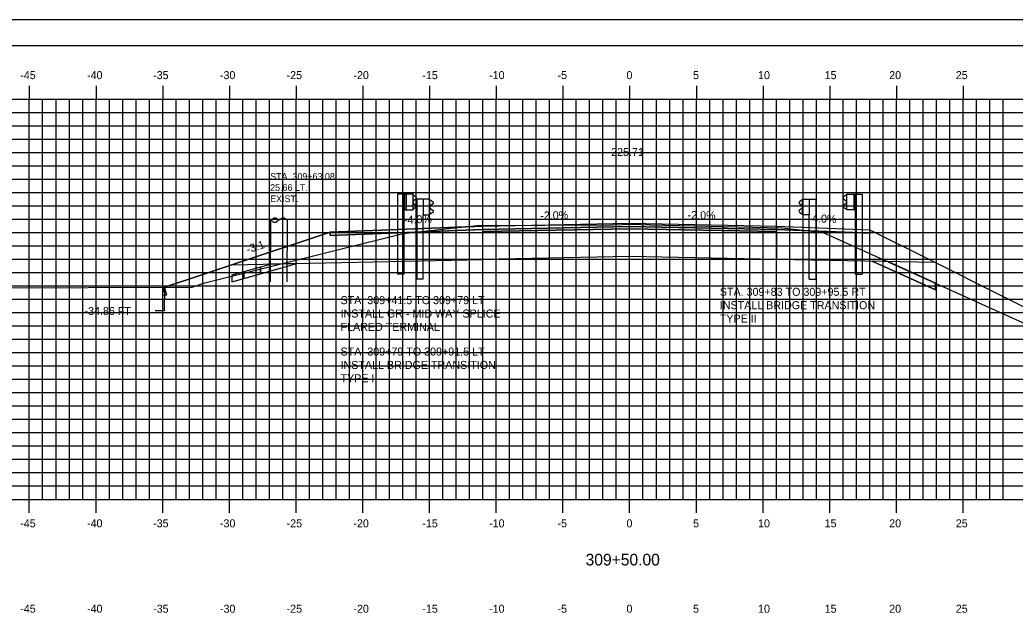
# Model space of a CAD drawing. Extents: x 1137876 to 1138046, y 608981 to 609091.
# Drawn here: x 1137913.5 to 1137988.1, y 609046.6 to 609091.3 of the extents above; entities that cross this region are included whole.
import ezdxf

# ---------------------------------------------------------------- set-up
doc = ezdxf.new("R2010")
doc.units = 0
for name, color, linetype in [('ANNOTATION', 7, 'Continuous'), ('BORDER', 7, 'Continuous'), ('D_Guardrail_Beam_Lt', 7, 'Continuous'), ('D_Guardrail_Beam_Rt', 7, 'Continuous'), ('D_Roadway_Centerline', 7, 'Continuous'), ('D_Roadway_Centerline_Text', 7, 'Continuous'), ('D_Roadway_Edge_Shoulder', 7, 'Continuous'), ('D_Roadway_Edge_TW', 7, 'Continuous'), ('D_Roadway_Pavement', 7, 'Continuous'), ('D_Roadway_SlopeLines', 7, 'Continuous'), ('D_Roadway_SubGrade', 7, 'Continuous'), ('D_Text_Monospaced', 7, 'Continuous'), ('D_Text_Standard', 7, 'Continuous'), ('H_V ANNOTATION', 7, 'Continuous'), ('MAJOR', 7, 'Continuous'), ('MINOR', 7, 'Continuous'), ('PLOT BOUNDARY', 7, 'Continuous'), ('S_Guardrail_Beam', 7, 'Continuous'), ('S_Roadway_Centerline', 7, 'Continuous'), ('S_Utilities_Pole_Power', 7, 'Continuous'), ('SHADING', 7, 'Continuous')]:
    doc.layers.add(name, color=color, linetype=linetype)

msp = doc.modelspace()

# ---------------------------------------------------------------- linework, layer by layer
msp.add_lwpolyline([(1137924.31, 609071.229), (1137926.339, 609071.906), (1137929.339, 609072.906), (1137936.714, 609075.364), (1137936.715, 609075.364), (1137948.166, 609075.822), (1137959.166, 609076.042), (1137970.166, 609075.822), (1137977.166, 609075.542), (1137982.083, 609073.084), (1137986.552, 609070.849), (1137995.165, 609066.543)])
at = {"layer": 'BORDER'}
msp.add_lwpolyline([(1137884.166, 608984.335), (1138044.166, 608984.335), (1138044.166, 609089.335), (1137884.166, 609089.335)], close=True, dxfattribs=at)
at = {"layer": 'D_Guardrail_Beam_Lt'}
for p, q in [((1137941.768, 609078.207), (1137941.768, 609072.207)), ((1137942.239, 609078.207), (1137941.768, 609078.207)), ((1137942.926, 609078.207), (1137942.239, 609078.207)), ((1137942.239, 609078.207), (1137942.239, 609077.04)), ((1137942.301, 609078.207), (1137942.301, 609077.04)), ((1137942.405, 609078.207), (1137942.405, 609077.04)), ((1137942.926, 609077.04), (1137942.926, 609078.207)), ((1137942.926, 609078.124), (1137943, 609078.109)), ((1137942.931, 609077.659), (1137942.931, 609077.589)), ((1137943.16, 609077.859), (1137942.964, 609077.723)), ((1137943.016, 609078.102), (1137943.16, 609078.003)), ((1137975.347, 609078.101), (1137975.203, 609078.001)), ((1137975.203, 609077.858), (1137975.399, 609077.722)), ((1137975.437, 609078.122), (1137975.363, 609078.108)), ((1137975.432, 609077.657), (1137975.432, 609077.587)), ((1137942.239, 609077.04), (1137942.926, 609077.04)), ((1137942.26, 609072.207), (1137942.26, 609077.04)), ((1137943, 609077.138), (1137942.926, 609077.124)), ((1137942.964, 609077.524), (1137943.16, 609077.388)), ((1137943.16, 609077.245), (1137943.016, 609077.145)), ((1137975.399, 609077.523), (1137975.203, 609077.386)), ((1137975.203, 609077.243), (1137975.347, 609077.143)), ((1137975.363, 609077.137), (1137975.437, 609077.122)), ((1137942.26, 609072.207), (1137941.768, 609072.207))]:
    msp.add_line(p, q, dxfattribs=at)
for centre, major_axis, start_param, end_param in [((1137943.01, 609077.659), (-0.0789, 0), 5.323254, 6.283185), ((1137942.992, 609078.069), (0.0417, 0), 0.959931, 1.376053), ((1137943.109, 609077.931), (0.0877, 0), 5.323254, 7.243116), ((1137975.254, 609077.929), (-0.0877, 0), 5.323254, 7.243116), ((1137975.371, 609078.067), (-0.0417, 0), 4.907132, 5.323254), ((1137975.353, 609077.657), (0.0789, 0), 0, 0.959931), ((1137943.01, 609077.589), (-0.0789, 0), 6.283185, 7.243116), ((1137942.992, 609077.179), (0.0417, 0), 4.907132, 5.323254), ((1137943.109, 609077.317), (0.0877, 0), 5.323254, 7.243116), ((1137975.254, 609077.315), (-0.0877, 0), 5.323254, 7.243116), ((1137975.371, 609077.177), (-0.0417, 0), 0.959931, 1.376053), ((1137975.353, 609077.587), (0.0789, 0), 5.323254, 6.283185)]:
    msp.add_ellipse(centre, major_axis=major_axis, ratio=0.995501, start_param=start_param, end_param=end_param, dxfattribs=at)
at = {"layer": 'D_Guardrail_Beam_Rt'}
for p, q in [((1137975.437, 609078.205), (1137976.124, 609078.205)), ((1137975.437, 609077.039), (1137975.437, 609078.205)), ((1137975.958, 609078.205), (1137975.958, 609077.039)), ((1137976.062, 609078.205), (1137976.062, 609077.039)), ((1137976.124, 609078.205), (1137976.595, 609078.205)), ((1137976.124, 609078.205), (1137976.124, 609077.039)), ((1137976.595, 609078.205), (1137976.595, 609072.205)), ((1137976.124, 609077.039), (1137975.437, 609077.039)), ((1137976.103, 609072.205), (1137976.103, 609077.039)), ((1137976.103, 609072.205), (1137976.595, 609072.205))]:
    msp.add_line(p, q, dxfattribs=at)
at = {"layer": 'D_Roadway_Edge_Shoulder'}
for points in [[(1137948.166, 609075.822), (1137936.715, 609075.364), (1137936.715, 609075.114), (1137948.166, 609075.572)], [(1137970.166, 609075.822), (1137977.166, 609075.542), (1137977.166, 609075.292), (1137970.166, 609075.572)]]:
    msp.add_lwpolyline(points, close=True, dxfattribs=at)
at = {"layer": 'D_Roadway_Edge_TW'}
msp.add_lwpolyline([(1137948.166, 609075.572), (1137948.166, 609075.822), (1137959.166, 609076.042), (1137970.166, 609075.822), (1137970.166, 609075.572), (1137959.166, 609075.792)], close=True, dxfattribs=at)
at = {"layer": 'D_Roadway_Pavement'}
msp.add_lwpolyline([(1137948.166, 609075.405), (1137948.166, 609075.572), (1137959.166, 609075.792), (1137970.166, 609075.572), (1137970.166, 609075.405), (1137959.166, 609075.625)], close=True, dxfattribs=at)
at = {"layer": 'D_Roadway_SlopeLines'}
for points in [[(1137982.083, 609071.538), (1137982.083, 609071.038), (1137977.351, 609073.178)], [(1137929.339, 609072.906), (1137926.339, 609071.906)], [(1137929.339, 609072.136), (1137929.339, 609071.636), (1137934.208, 609073.003)], [(1137982.083, 609073.084), (1137986.552, 609070.849)], [(1137926.339, 609071.906), (1137924.31, 609071.229)], [(1137986.552, 609070.849), (1137995.165, 609066.543)]]:
    msp.add_lwpolyline(points, dxfattribs=at)
at = {"layer": 'D_Roadway_SubGrade'}
for points in [[(1137948.166, 609075.405), (1137948.166, 609075.572), (1137936.715, 609075.114), (1137936.715, 609075.364), (1137936.714, 609075.364), (1137929.339, 609072.906), (1137948.166, 609073.322)], [(1137948.166, 609073.322), (1137948.166, 609075.405), (1137959.166, 609075.625), (1137970.166, 609075.405), (1137970.166, 609073.322), (1137959.166, 609073.542)], [(1137970.166, 609075.405), (1137970.166, 609075.572), (1137977.166, 609075.292), (1137977.166, 609075.542), (1137977.166, 609075.542), (1137982.083, 609073.084), (1137970.166, 609073.322)]]:
    msp.add_lwpolyline(points, close=True, dxfattribs=at)
at = {"layer": 'D_Text_Standard'}
msp.add_lwpolyline([(1137924.31, 609071.229), (1137924.285, 609069.455), (1137923.605, 609069.455)], dxfattribs=at)
msp.add_lwpolyline([(1137924.31, 609071.229), (1137924.447, 609070.645), (1137924.156, 609070.649)], close=True, dxfattribs=at)
at = {"layer": 'MAJOR'}
for p, q in [((1137914.166, 609086.337), (1137914.166, 609085.335)), ((1137919.166, 609086.337), (1137919.166, 609085.335)), ((1137924.166, 609086.337), (1137924.166, 609085.335)), ((1137929.166, 609086.337), (1137929.166, 609085.335)), ((1137934.166, 609086.337), (1137934.166, 609085.335)), ((1137939.166, 609086.337), (1137939.166, 609085.335)), ((1137944.166, 609086.337), (1137944.166, 609085.335)), ((1137949.166, 609086.337), (1137949.166, 609085.335)), ((1137954.166, 609086.337), (1137954.166, 609085.335)), ((1137959.166, 609086.337), (1137959.166, 609085.335)), ((1137964.166, 609086.337), (1137964.166, 609085.335)), ((1137969.166, 609086.337), (1137969.166, 609085.335)), ((1137974.166, 609086.337), (1137974.166, 609085.335)), ((1137979.166, 609086.337), (1137979.166, 609085.335)), ((1137984.166, 609086.337), (1137984.166, 609085.335)), ((1137889.166, 609085.335), (1138029.166, 609085.335)), ((1137889.166, 609085.335), (1138029.166, 609085.335)), ((1137914.166, 609055.335), (1137914.166, 609085.335)), ((1137919.166, 609055.335), (1137919.166, 609085.335)), ((1137924.166, 609055.335), (1137924.166, 609085.335)), ((1137929.166, 609055.335), (1137929.166, 609085.335)), ((1137934.166, 609055.335), (1137934.166, 609085.335)), ((1137939.166, 609055.335), (1137939.166, 609085.335)), ((1137944.166, 609055.335), (1137944.166, 609085.335)), ((1137949.166, 609055.335), (1137949.166, 609085.335)), ((1137954.166, 609055.335), (1137954.166, 609085.335)), ((1137959.166, 609055.335), (1137959.166, 609085.335)), ((1137964.166, 609055.335), (1137964.166, 609085.335)), ((1137969.166, 609055.335), (1137969.166, 609085.335)), ((1137974.166, 609055.335), (1137974.166, 609085.335)), ((1137979.166, 609055.335), (1137979.166, 609085.335)), ((1137984.166, 609055.335), (1137984.166, 609085.335)), ((1137889.166, 609080.335), (1138029.166, 609080.335)), ((1137889.166, 609075.335), (1138029.166, 609075.335)), ((1137889.166, 609070.335), (1138029.166, 609070.335)), ((1137889.166, 609065.335), (1138029.166, 609065.335)), ((1137889.166, 609060.335), (1138029.166, 609060.335)), ((1137889.166, 609055.335), (1138029.166, 609055.335)), ((1137889.166, 609055.335), (1138029.166, 609055.335)), ((1137914.166, 609054.333), (1137914.166, 609055.335)), ((1137919.166, 609054.333), (1137919.166, 609055.335)), ((1137924.166, 609054.333), (1137924.166, 609055.335)), ((1137929.166, 609054.333), (1137929.166, 609055.335)), ((1137934.166, 609054.333), (1137934.166, 609055.335)), ((1137939.166, 609054.333), (1137939.166, 609055.335)), ((1137944.166, 609054.333), (1137944.166, 609055.335)), ((1137949.166, 609054.333), (1137949.166, 609055.335)), ((1137954.166, 609054.333), (1137954.166, 609055.335)), ((1137959.166, 609054.333), (1137959.166, 609055.335)), ((1137964.166, 609054.333), (1137964.166, 609055.335)), ((1137969.166, 609054.333), (1137969.166, 609055.335)), ((1137974.166, 609054.333), (1137974.166, 609055.335)), ((1137979.166, 609054.333), (1137979.166, 609055.335)), ((1137984.166, 609054.333), (1137984.166, 609055.335))]:
    msp.add_line(p, q, dxfattribs=at)
at = {"layer": 'MINOR'}
for p, q in [((1137915.166, 609055.335), (1137915.166, 609085.335)), ((1137916.166, 609055.335), (1137916.166, 609085.335)), ((1137917.166, 609055.335), (1137917.166, 609085.335)), ((1137918.166, 609055.335), (1137918.166, 609085.335)), ((1137920.166, 609055.335), (1137920.166, 609085.335)), ((1137921.166, 609055.335), (1137921.166, 609085.335)), ((1137922.166, 609055.335), (1137922.166, 609085.335)), ((1137923.166, 609055.335), (1137923.166, 609085.335)), ((1137925.166, 609055.335), (1137925.166, 609085.335)), ((1137926.166, 609055.335), (1137926.166, 609085.335)), ((1137927.166, 609055.335), (1137927.166, 609085.335)), ((1137928.166, 609055.335), (1137928.166, 609085.335)), ((1137930.166, 609055.335), (1137930.166, 609085.335)), ((1137931.166, 609055.335), (1137931.166, 609085.335)), ((1137932.166, 609055.335), (1137932.166, 609085.335)), ((1137933.166, 609055.335), (1137933.166, 609085.335)), ((1137935.166, 609055.335), (1137935.166, 609085.335)), ((1137936.166, 609055.335), (1137936.166, 609085.335)), ((1137937.166, 609055.335), (1137937.166, 609085.335)), ((1137938.166, 609055.335), (1137938.166, 609085.335)), ((1137940.166, 609055.335), (1137940.166, 609085.335)), ((1137941.166, 609055.335), (1137941.166, 609085.335)), ((1137942.166, 609055.335), (1137942.166, 609085.335)), ((1137943.166, 609055.335), (1137943.166, 609085.335)), ((1137945.166, 609055.335), (1137945.166, 609085.335)), ((1137946.166, 609055.335), (1137946.166, 609085.335)), ((1137947.166, 609055.335), (1137947.166, 609085.335)), ((1137948.166, 609055.335), (1137948.166, 609085.335)), ((1137950.166, 609055.335), (1137950.166, 609085.335)), ((1137951.166, 609055.335), (1137951.166, 609085.335)), ((1137952.166, 609055.335), (1137952.166, 609085.335)), ((1137953.166, 609055.335), (1137953.166, 609085.335)), ((1137955.166, 609055.335), (1137955.166, 609085.335)), ((1137956.166, 609055.335), (1137956.166, 609085.335)), ((1137957.166, 609055.335), (1137957.166, 609085.335)), ((1137958.166, 609055.335), (1137958.166, 609085.335)), ((1137960.166, 609055.335), (1137960.166, 609085.335)), ((1137961.166, 609055.335), (1137961.166, 609085.335)), ((1137962.166, 609055.335), (1137962.166, 609085.335)), ((1137963.166, 609055.335), (1137963.166, 609085.335)), ((1137965.166, 609055.335), (1137965.166, 609085.335)), ((1137966.166, 609055.335), (1137966.166, 609085.335)), ((1137967.166, 609055.335), (1137967.166, 609085.335)), ((1137968.166, 609055.335), (1137968.166, 609085.335)), ((1137970.166, 609055.335), (1137970.166, 609085.335)), ((1137971.166, 609055.335), (1137971.166, 609085.335)), ((1137972.166, 609055.335), (1137972.166, 609085.335)), ((1137973.166, 609055.335), (1137973.166, 609085.335)), ((1137975.166, 609055.335), (1137975.166, 609085.335)), ((1137976.166, 609055.335), (1137976.166, 609085.335)), ((1137977.166, 609055.335), (1137977.166, 609085.335)), ((1137978.166, 609055.335), (1137978.166, 609085.335)), ((1137980.166, 609055.335), (1137980.166, 609085.335)), ((1137981.166, 609055.335), (1137981.166, 609085.335)), ((1137982.166, 609055.335), (1137982.166, 609085.335)), ((1137983.166, 609055.335), (1137983.166, 609085.335)), ((1137985.166, 609055.335), (1137985.166, 609085.335)), ((1137986.166, 609055.335), (1137986.166, 609085.335)), ((1137987.166, 609055.335), (1137987.166, 609085.335)), ((1137889.166, 609084.335), (1138029.166, 609084.335)), ((1137889.166, 609083.335), (1138029.166, 609083.335)), ((1137889.166, 609082.335), (1138029.166, 609082.335)), ((1137889.166, 609081.335), (1138029.166, 609081.335)), ((1137889.166, 609079.335), (1138029.166, 609079.335)), ((1137889.166, 609078.335), (1138029.166, 609078.335)), ((1137889.166, 609077.335), (1138029.166, 609077.335)), ((1137889.166, 609076.335), (1138029.166, 609076.335)), ((1137889.166, 609074.335), (1138029.166, 609074.335)), ((1137889.166, 609073.335), (1138029.166, 609073.335)), ((1137889.166, 609072.335), (1138029.166, 609072.335)), ((1137889.166, 609071.335), (1138029.166, 609071.335)), ((1137889.166, 609069.335), (1138029.166, 609069.335)), ((1137889.166, 609068.335), (1138029.166, 609068.335)), ((1137889.166, 609067.335), (1138029.166, 609067.335)), ((1137889.166, 609066.335), (1138029.166, 609066.335)), ((1137889.166, 609064.335), (1138029.166, 609064.335)), ((1137889.166, 609063.335), (1138029.166, 609063.335)), ((1137889.166, 609062.335), (1138029.166, 609062.335)), ((1137889.166, 609061.335), (1138029.166, 609061.335)), ((1137889.166, 609059.335), (1138029.166, 609059.335)), ((1137889.166, 609058.335), (1138029.166, 609058.335)), ((1137889.166, 609057.335), (1138029.166, 609057.335)), ((1137889.166, 609056.335), (1138029.166, 609056.335))]:
    msp.add_line(p, q, dxfattribs=at)
at = {"layer": 'PLOT BOUNDARY'}
msp.add_lwpolyline([(1137876.073, 608981.276), (1138046.073, 608981.276), (1138046.073, 609091.276), (1137876.073, 609091.276)], close=True, dxfattribs=at)
at = {"layer": 'S_Guardrail_Beam'}
for p, q in [((1137943.205, 609077.828), (1137943.205, 609071.828)), ((1137943.697, 609077.828), (1137943.205, 609077.828)), ((1137944.187, 609077.828), (1137943.697, 609077.828)), ((1137943.697, 609077.828), (1137943.697, 609076.661)), ((1137944.187, 609076.661), (1137944.187, 609077.828)), ((1137944.187, 609077.755), (1137944.269, 609077.74)), ((1137944.285, 609077.733), (1137944.429, 609077.633)), ((1137972.032, 609077.747), (1137971.889, 609077.647)), ((1137972.131, 609077.768), (1137972.049, 609077.754)), ((1137972.131, 609077.841), (1137972.62, 609077.841)), ((1137972.131, 609076.674), (1137972.131, 609077.841)), ((1137972.62, 609077.841), (1137973.112, 609077.841)), ((1137972.62, 609077.841), (1137972.62, 609076.674)), ((1137973.112, 609077.841), (1137973.112, 609071.841)), ((1137944.2, 609077.29), (1137944.2, 609077.199)), ((1137944.429, 609077.49), (1137944.233, 609077.354)), ((1137944.233, 609077.134), (1137944.429, 609076.998)), ((1137971.889, 609077.504), (1137972.084, 609077.367)), ((1137972.084, 609077.148), (1137971.889, 609077.011)), ((1137972.118, 609077.303), (1137972.118, 609077.212)), ((1137943.697, 609071.828), (1137943.697, 609076.661)), ((1137943.697, 609076.661), (1137944.187, 609076.661)), ((1137944.269, 609076.748), (1137944.187, 609076.734)), ((1137944.429, 609076.855), (1137944.285, 609076.755)), ((1137971.889, 609076.868), (1137972.032, 609076.768)), ((1137972.049, 609076.762), (1137972.131, 609076.747)), ((1137972.62, 609076.674), (1137972.131, 609076.674)), ((1137972.62, 609071.841), (1137972.62, 609076.674)), ((1137943.697, 609071.828), (1137943.205, 609071.828)), ((1137972.62, 609071.841), (1137973.112, 609071.841))]:
    msp.add_line(p, q, dxfattribs=at)
for centre, major_axis, start_param, end_param in [((1137944.261, 609077.699), (0.0417, 0), 0.959931, 1.396263), ((1137944.378, 609077.562), (0.0877, 0), 5.323254, 7.243116), ((1137971.939, 609077.575), (-0.0877, 0), 5.323254, 7.243116), ((1137972.056, 609077.713), (-0.0417, 0), 4.886922, 5.323254), ((1137944.279, 609077.29), (-0.0789, 0), 5.323254, 6.283185), ((1137944.279, 609077.199), (-0.0789, 0), 6.283185, 7.243116), ((1137944.378, 609076.927), (0.0877, 0), 5.323254, 7.243116), ((1137971.939, 609076.94), (-0.0877, 0), 5.323254, 7.243116), ((1137972.039, 609077.303), (0.0789, 0), 0, 0.959931), ((1137972.039, 609077.212), (0.0789, 0), 5.323254, 6.283185), ((1137944.261, 609076.789), (0.0417, 0), 4.886922, 5.323254), ((1137972.056, 609076.802), (-0.0417, 0), 0.959931, 1.396263)]:
    msp.add_ellipse(centre, major_axis=major_axis, ratio=0.995501, start_param=start_param, end_param=end_param, dxfattribs=at)
at = {"layer": 'S_Roadway_Centerline'}
msp.add_lwpolyline([(1137889.166, 609070.313), (1137894.157, 609070.541), (1137907.419, 609071.161), (1137910.439, 609071.192), (1137910.786, 609071.181), (1137926.383, 609071.246), (1137927.333, 609071.573), (1137942.192, 609075.263), (1137946.056, 609075.698), (1137947.752, 609075.86), (1137957.882, 609075.908), (1137959.356, 609075.955), (1137960.699, 609075.902), (1137970.583, 609075.689), (1137973.493, 609075.356), (1137973.722, 609075.319), (1137986.058, 609069.74), (1137991.281, 609067.381), (1137992.629, 609067.183), (1137998.236, 609065.767), (1138001.572, 609065.613), (1138013.791, 609064.771), (1138025.425, 609064.464), (1138029.166, 609064.258)], dxfattribs=at)
at = {"layer": 'S_Utilities_Pole_Power'}
for p, q in [((1137932.255, 609076.265), (1137932.411, 609076.375)), ((1137932.255, 609071.645), (1137932.258, 609076.265)), ((1137932.411, 609076.154), (1137932.255, 609076.265)), ((1137932.724, 609076.375), (1137932.88, 609076.265)), ((1137932.88, 609076.265), (1137932.724, 609076.154)), ((1137933.037, 609076.375), (1137932.88, 609076.265)), ((1137933.505, 609076.265), (1137933.349, 609076.375)), ((1137933.505, 609071.645), (1137933.508, 609076.265))]:
    msp.add_line(p, q, dxfattribs=at)
for centre, start, end in [((1137932.568, 609076.154), 90, 125.26439), ((1137932.568, 609076.375), 234.73561, 270), ((1137932.568, 609076.154), 54.73561, 90), ((1137932.568, 609076.375), 270, 305.26439), ((1137933.193, 609076.154), 90, 125.26439), ((1137933.193, 609076.154), 54.73561, 90)]:
    msp.add_arc(centre, 0.271, start, end, dxfattribs=at)
at = {"layer": 'SHADING'}
for p, q in [((1137978.507, 609073.155), (1137977.351, 609073.178)), ((1137931.506, 609072.744), (1137930.256, 609072.393)), ((1137931.506, 609072.244), (1137934.208, 609073.003)), ((1137932.291, 609072.965), (1137931.506, 609072.744)), ((1137931.506, 609072.744), (1137931.506, 609072.244)), ((1137931.506, 609072.244), (1137931.506, 609072.744)), ((1137934.208, 609073.003), (1137932.291, 609072.965)), ((1137982.083, 609071.538), (1137978.507, 609073.155)), ((1137930.256, 609072.393), (1137929.339, 609072.136)), ((1137930.256, 609072.393), (1137930.255, 609071.893)), ((1137930.255, 609071.893), (1137930.256, 609072.393)), ((1137930.255, 609071.893), (1137931.506, 609072.244))]:
    msp.add_line(p, q, dxfattribs=at)
for points in [[(1137977.351, 609073.178), (1137982.083, 609071.038), (1137982.083, 609071.538)], [(1137929.339, 609072.136), (1137929.339, 609071.636), (1137930.255, 609071.893)]]:
    msp.add_lwpolyline(points, dxfattribs=at)

# ---------------------------------------------------------------- texts
at = {"layer": 'ANNOTATION'}
for s, rotation, p in [('-2.0%', 1.14576, (1137952.469, 609076.308)), ('-2.0%', 358.85424, (1137963.509, 609076.355)), ('-4.0%', 2.29061, (1137942.257, 609075.987)), ('-4.0%', 357.70939, (1137972.562, 609076.127)), ('-3:1', 18.43483, (1137930.544, 609073.761))]:
    msp.add_text(s, height=0.6, rotation=rotation, dxfattribs=at).set_placement(p)
for s, p in [('STA. 309+83 TO 309+95.5 RT', (1137965.925, 609070.593)), ('STA. 309+41.5 TO 309+79 LT', (1137937.495, 609069.966)), ('INSTALL BRIDGE TRANSITION', (1137965.925, 609069.591)), ('INSTALL GR - MID WAY SPLICE', (1137937.495, 609068.964)), ('TYPE II', (1137965.925, 609068.589)), ('FLARED TERMINAL', (1137937.495, 609067.962)), ('STA. 309+79 TO 309+91.5 LT', (1137937.495, 609066.114)), ('INSTALL BRIDGE TRANSITION', (1137937.495, 609065.112)), ('TYPE II', (1137937.495, 609064.11))]:
    msp.add_text(s, height=0.6, dxfattribs=at).set_placement(p)
at = {"layer": 'D_Roadway_Centerline'}
for s, p in [('C', (1137959.161, 609076.042)), ('L', (1137959.166, 609076.035))]:
    msp.add_text(s, height=0.0146, dxfattribs=at).set_placement(p)
at = {"layer": 'D_Roadway_Centerline_Text'}
msp.add_text('225.71', height=0.6, dxfattribs=at).set_placement((1137957.78, 609081.074))
at = {"layer": 'D_Text_Monospaced'}
for s, height, p in [('STA. 309+63.08', 0.49998, (1137932.218, 609079.291)), ('25.66 LT.', 0.5, (1137932.218, 609078.457)), ('EXIST. ', 0.5, (1137932.218, 609077.617))]:
    msp.add_text(s, height=height, dxfattribs=at).set_placement(p)
at = {"layer": 'D_Text_Standard'}
msp.add_text('-34.86 FT', height=0.6, dxfattribs=at).set_placement((1137918.3, 609069.155))
at = {"layer": 'H_V ANNOTATION'}
for s, height, p in [('-45', 0.6, (1137913.484, 609086.835)), ('-40', 0.6, (1137918.492, 609086.835)), ('-35', 0.6, (1137923.446, 609086.835)), ('-30', 0.6, (1137928.454, 609086.835)), ('-25', 0.6, (1137933.451, 609086.835)), ('-20', 0.6, (1137938.459, 609086.835)), ('-15', 0.6, (1137943.623, 609086.835)), ('-10', 0.6, (1137948.631, 609086.835)), ('-5', 0.6, (1137953.757, 609086.835)), ('0', 0.6, (1137958.925, 609086.835)), ('5', 0.6, (1137963.917, 609086.835)), ('10', 0.6, (1137968.791, 609086.835)), ('15', 0.6, (1137973.783, 609086.835)), ('20', 0.6, (1137978.62, 609086.835)), ('25', 0.6, (1137983.612, 609086.835)), ('-45', 0.6, (1137913.484, 609053.235)), ('-40', 0.6, (1137918.492, 609053.235)), ('-35', 0.6, (1137923.446, 609053.235)), ('-30', 0.6, (1137928.454, 609053.235)), ('-25', 0.6, (1137933.451, 609053.235)), ('-20', 0.6, (1137938.459, 609053.235)), ('-15', 0.6, (1137943.623, 609053.235)), ('-10', 0.6, (1137948.631, 609053.235)), ('-5', 0.6, (1137953.757, 609053.235)), ('0', 0.6, (1137958.925, 609053.235)), ('5', 0.6, (1137963.917, 609053.235)), ('10', 0.6, (1137968.791, 609053.235)), ('15', 0.6, (1137973.783, 609053.235)), ('20', 0.6, (1137978.62, 609053.235)), ('25', 0.6, (1137983.612, 609053.235)), ('309+50.00', 0.875, (1137955.865, 609050.378)), ('-45', 0.6, (1137913.484, 609046.835)), ('-40', 0.6, (1137918.492, 609046.835)), ('-35', 0.6, (1137923.446, 609046.835)), ('-30', 0.6, (1137928.454, 609046.835)), ('-25', 0.6, (1137933.451, 609046.835)), ('-20', 0.6, (1137938.459, 609046.835)), ('-15', 0.6, (1137943.623, 609046.835)), ('-10', 0.6, (1137948.631, 609046.835)), ('-5', 0.6, (1137953.757, 609046.835)), ('0', 0.6, (1137958.925, 609046.835)), ('5', 0.6, (1137963.917, 609046.835)), ('10', 0.6, (1137968.791, 609046.835)), ('15', 0.6, (1137973.783, 609046.835)), ('20', 0.6, (1137978.62, 609046.835)), ('25', 0.6, (1137983.612, 609046.835))]:
    msp.add_text(s, height=height, dxfattribs=at).set_placement(p)
at = {"layer": 'S_Roadway_Centerline'}
for s, p in [('C', (1137959.351, 609075.955)), ('L', (1137959.356, 609075.948))]:
    msp.add_text(s, height=0.0146, dxfattribs=at).set_placement(p)

doc.saveas('drawing.dxf')
